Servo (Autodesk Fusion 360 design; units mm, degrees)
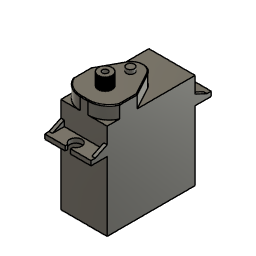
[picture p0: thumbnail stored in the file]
sketch "Esquisse3" plane through (0, 0, 0) normal (1, 0, 0) x axis (0, 0, -1)
  line L1 (0, 0) -> (0, 18.4)
  line L2 (23.4, 0) -> (0, 0)
  line L3 (23.4, 18.4) -> (23.4, 0)
  line L4 (27.7, 18.4) -> (23.4, 18.4)
  line L5 (27.7, 19.6) -> (27.7, 18.4)
  line L6 (26.5623, 19.6) -> (27.7, 19.6)
  line L7 (23.4, 21.1) -> (26.5623, 19.6)
  line L8 (23.4, 25.4) -> (23.4, 21.1)
  line L9 (0, 25.4) -> (23.4, 25.4)
  line L10 (0, 21.1) -> (0, 25.4)
  line L11 (-3.1623, 19.6) -> (0, 21.1)
  line L12 (-4.3, 19.6) -> (-3.1623, 19.6)
  line L13 (-4.3, 18.4) -> (-4.3, 19.6)
  line L14 (0, 18.4) -> (-4.3, 18.4)
  point P2 (0, 18.4)
  point P16 (0, 18.4)
  point P12 (0, 21.1)
  point P5 (23.4, 18.4)
  point P9 (23.4, 21.1)
  point P8 (26.5623, 19.6)
  point P13 (-3.1623, 19.6)
  point P1 (0, 0)
  point P3 (0, 0)
  point P14 (-4.3, 19.6)
  point P15 (-4.3, 18.4)
  vertical L1
  perpendicular L1 L2
  perpendicular L2 L3
  perpendicular L3 L4
  perpendicular L4 L5
  perpendicular L5 L6
  perpendicular L6 L8
  perpendicular L8 L9
  perpendicular L9 L10
  perpendicular L10 L12
  perpendicular L12 L13
  perpendicular L13 L14
  coincident P2 P16
  vertical P2 P12
  vertical P5 P9
  equal L5 L13
  horizontal P8 P13
  equal L7 L11
  equal L10 L14
  equal L4 L14
  coincident P1 P3
  equal L8 L10
  dimension "d1" distance L1 L3 = 23.4
  dimension "d2" distance L2 L9 = 25.4
  dimension "d3" distance L5 L13 = 32
  dimension "d4" distance P14 P15 = 1.2
  dimension "d5" distance P12 L14 = 2.7
  dimension "d6" distance P12 P13 = 3.5
extrude "Extrusion1" new body sketch "Esquisse3" along normal blind 6.15 (= "( 12.3 / 2 ) * 1 mm") and against normal blind 6.15 (= "( 12.3 / 2 ) * 1 mm")
sketch "Esquisse4" plane through (0, 25.4, 0) normal (0, 1, 0) x axis (-1, 0, 0)
  line L1 (-6.15, 0) -> (6.15, 0)
  line L2 (-6.15, -23.4) -> (-6.15, 0)
  line L3 (6.15, -23.4) -> (-6.15, -23.4)
  line L4 (6.15, 0) -> (6.15, -23.4)
  line L5 (6.15, -3.2909) -> (6.15, -7.9909)
  line L6 (0, 0) -> (1.0315, 0)
  line L7 (2.8, -14.1372) -> (6.15, -7.9909)
  line L8 (-9.0575, -15.8) -> (8.378, -15.8)
  line L9 (0, 22.5) -> (0, 1.75)
  line L10 (-2.8, -14.1372) -> (-6.15, -7.9909)
  line L11 (-6.15, -3.2909) -> (-6.15, -7.9909)
  arc A1 centre (1.0315, -5.6261) radius 5.6261 clockwise from (1.0315, 0) to (6.15, -3.2909)
  arc A2 centre (0, -12.6111) radius 3.1889 clockwise from (2.8, -14.1372) to (0, -15.8)
  arc A3 centre (0, -12.6111) radius 3.1889 clockwise from (0, -15.8) to (-2.8, -14.1372)
  arc A4 centre (-1.0315, -5.6261) radius 5.6261 clockwise from (-6.15, -3.2909) to (-1.0315, 0)
  point P6 (6.15, -7.9909)
  point P7 (6.15, -3.2909)
  point P1 (0, 0)
  point P10 (0, 0)
  point P12 (0, -15.8)
  point P21 (-6.15, -7.9909)
  point P22 (-6.15, -3.2909)
  point P8 (1.0315, 0)
  point P24 (-1.0315, 0)
  point P11 (2.8, -14.1372)
  point P20 (-2.8, -14.1372)
  point P19 (0, -15.8)
  coincident L4 P6
  coincident L4 P7
  perpendicular L2 L6
  vertical P1 P10
  coincident P1 P10
  vertical P1 P12
  tangent L7 A2
  perpendicular L4 L8
  tangent A2 L8
  coincident P12 L8
  collinear L4 L5
  tangent A1 L7
  tangent A1 L6
  symmetric P6 L9 P21
  symmetric P7 L9 P22
  symmetric P8 L9 P24
  symmetric A1 L9 A4
  symmetric P11 L9 P20
  symmetric P12 L9 P19
  symmetric A2 L9 A3
  dimension "d11" distance L6 L8 = 15.8
  dimension "d13" distance P6 P7 = 4.7
  dimension "d15" distance P6 P11 = 7
  dimension "d16" distance P11 L9 = 2.8 (= "( 5.6 / 2 ) * 1 mm")
extrude "Extrusion2" add sketch "Esquisse4" profile of L1 L2 L4 L5 A1 L6 L7 A2 A3 L10 L11 A4 along normal blind 3.4
sketch "Esquisse5" plane through (0, 28.8, 0) normal (0, 1, 0) x axis (-1, 0, 0)
  line L1 (6.15, -3.2909) -> (6.15, -7.9909)
  line L2 (-1.0315, 0) -> (1.0315, 0)
  line L3 (-6.15, -7.9909) -> (-6.15, -3.2909)
  line L4 (-2.8, -14.1372) -> (-6.15, -7.9909)
  line L5 (6.15, -7.9909) -> (2.8, -14.1372)
  line L6 (0, 22.5) -> (0, 1.75)
  line L7 (-2.5, -13.4) -> (1.9579, -13.4)
  line L8 (-3, -15.8) -> (2.2631, -15.8)
  arc A1 centre (1.0315, -5.6261) radius 5.6261 clockwise from (1.0315, 0) to (6.15, -3.2909)
  arc A2 centre (-1.0315, -5.6261) radius 5.6261 clockwise from (-6.15, -3.2909) to (-1.0315, 0)
  arc A3 centre (0, -12.6111) radius 3.1889 clockwise from (2.8, -14.1372) to (-2.8, -14.1372)
  circle C1 centre (0, -12.35) radius 1.05
  point P13 (0, -12.35)
  coincident P13 L6
  horizontal L7
  tangent C1 L7
  horizontal L8
  tangent A3 L8
  dimension "d19" diameter C1 = 2.1
  dimension "d20" distance L7 L8 = 2.4
extrude "Extrusion3" add sketch "Esquisse5" profile of C1 along normal blind 1.1
sketch "Esquisse6" plane through (0, 28.8, 0) normal (0, 1, 0) x axis (-1, 0, 0)
  line L1 (6.15, -3.2909) -> (6.15, -7.9909)
  line L2 (-1.0315, 0) -> (1.0315, 0)
  line L3 (-6.15, -7.9909) -> (-6.15, -3.2909)
  line L4 (-2.8, -14.1372) -> (-6.15, -7.9909)
  line L5 (6.15, -7.9909) -> (2.8, -14.1372)
  circle C1 centre (0, -12.35) radius 1.05
  arc A1 centre (1.0315, -5.6261) radius 5.6261 clockwise from (1.0315, 0) to (6.15, -3.2909)
  arc A2 centre (-1.0315, -5.6261) radius 5.6261 clockwise from (-6.15, -3.2909) to (-1.0315, 0)
  arc A3 centre (0, -12.6111) radius 3.1889 clockwise from (2.8, -14.1372) to (-2.8, -14.1372)
  circle C2 centre (0.0217, -5.6409) radius 1.85
  arc A4 centre (0.0217, -7.5545) radius 0.12 clockwise from (-0.0783, -7.4882) to (0.1217, -7.4882)
  arc A5 centre (0.3211, -7.5309) radius 0.12 clockwise from (0.2119, -7.4811) to (0.4095, -7.4498)
  arc A6 centre (0.6131, -7.4608) radius 0.12 clockwise from (0.4975, -7.4287) to (0.6877, -7.3669)
  arc A7 centre (0.8905, -7.3459) radius 0.12 clockwise from (0.7713, -7.3322) to (0.9495, -7.2414)
  arc A8 centre (1.1465, -7.189) radius 0.12 clockwise from (1.0266, -7.1942) to (1.1884, -7.0766)
  arc A9 centre (1.3749, -6.994) radius 0.12 clockwise from (1.2572, -7.0178) to (1.3987, -6.8764)
  arc A10 centre (1.5699, -6.7657) radius 0.12 clockwise from (1.4574, -6.8076) to (1.575, -6.6458)
  arc A11 centre (1.7268, -6.5097) radius 0.12 clockwise from (1.6223, -6.5686) to (1.7131, -6.3904)
  arc A12 centre (1.8417, -6.2322) radius 0.12 clockwise from (1.7477, -6.3068) to (1.8095, -6.1166)
  arc A13 centre (1.9118, -5.9402) radius 0.12 clockwise from (1.8306, -6.0286) to (1.8619, -5.8311)
  arc A14 centre (1.9354, -5.6409) radius 0.12 clockwise from (1.869, -5.7409) to (1.869, -5.5409)
  arc A15 centre (1.9118, -5.3415) radius 0.12 clockwise from (1.8619, -5.4507) to (1.8306, -5.2531)
  arc A16 centre (1.8417, -5.0495) radius 0.12 clockwise from (1.8095, -5.1651) to (1.7477, -4.9749)
  arc A17 centre (1.7268, -4.7721) radius 0.12 clockwise from (1.7131, -4.8913) to (1.6223, -4.7131)
  arc A18 centre (1.5699, -4.5161) radius 0.12 clockwise from (1.575, -4.636) to (1.4574, -4.4742)
  arc A19 centre (1.3749, -4.2877) radius 0.12 clockwise from (1.3987, -4.4054) to (1.2572, -4.2639)
  arc A20 centre (1.1465, -4.0927) radius 0.12 clockwise from (1.1884, -4.2052) to (1.0266, -4.0876)
  arc A21 centre (0.8905, -3.9358) radius 0.12 clockwise from (0.9495, -4.0403) to (0.7713, -3.9495)
  arc A22 centre (0.6131, -3.8209) radius 0.12 clockwise from (0.6877, -3.9149) to (0.4975, -3.8531)
  arc A23 centre (0.3211, -3.7508) radius 0.12 clockwise from (0.4095, -3.832) to (0.2119, -3.8007)
  arc A24 centre (0.0217, -3.7273) radius 0.12 clockwise from (0.1217, -3.7936) to (-0.0783, -3.7936)
  arc A25 centre (-0.2776, -3.7508) radius 0.12 clockwise from (-0.1685, -3.8007) to (-0.366, -3.832)
  arc A26 centre (-0.5696, -3.8209) radius 0.12 clockwise from (-0.454, -3.8531) to (-0.6442, -3.9149)
  arc A27 centre (-0.847, -3.9358) radius 0.12 clockwise from (-0.7278, -3.9495) to (-0.906, -4.0403)
  arc A28 centre (-1.1031, -4.0927) radius 0.12 clockwise from (-0.9832, -4.0876) to (-1.145, -4.2052)
  arc A29 centre (-1.3314, -4.2877) radius 0.12 clockwise from (-1.2138, -4.2639) to (-1.3552, -4.4054)
  arc A30 centre (-1.5264, -4.5161) radius 0.12 clockwise from (-1.414, -4.4742) to (-1.5315, -4.636)
  arc A31 centre (-1.6833, -4.7721) radius 0.12 clockwise from (-1.5788, -4.7131) to (-1.6696, -4.8913)
  arc A32 centre (-1.7982, -5.0495) radius 0.12 clockwise from (-1.7043, -4.9749) to (-1.7661, -5.1651)
  arc A33 centre (-1.8683, -5.3415) radius 0.12 clockwise from (-1.7872, -5.2531) to (-1.8185, -5.4507)
  arc A34 centre (-1.8919, -5.6409) radius 0.12 clockwise from (-1.8256, -5.5409) to (-1.8256, -5.7409)
  arc A35 centre (-1.8683, -5.9402) radius 0.12 clockwise from (-1.8185, -5.8311) to (-1.7872, -6.0286)
  arc A36 centre (-1.7982, -6.2322) radius 0.12 clockwise from (-1.7661, -6.1166) to (-1.7043, -6.3068)
  arc A37 centre (-1.6833, -6.5097) radius 0.12 clockwise from (-1.6696, -6.3904) to (-1.5788, -6.5686)
  arc A38 centre (-1.5264, -6.7657) radius 0.12 clockwise from (-1.5315, -6.6458) to (-1.414, -6.8076)
  arc A39 centre (-1.3314, -6.994) radius 0.12 clockwise from (-1.3552, -6.8764) to (-1.2138, -7.0178)
  arc A40 centre (-1.1031, -7.189) radius 0.12 clockwise from (-1.145, -7.0766) to (-0.9832, -7.1942)
  arc A41 centre (-0.847, -7.3459) radius 0.12 clockwise from (-0.906, -7.2414) to (-0.7278, -7.3322)
  arc A42 centre (-0.5696, -7.4608) radius 0.12 clockwise from (-0.6442, -7.3669) to (-0.454, -7.4287)
  arc A43 centre (-0.2776, -7.5309) radius 0.12 clockwise from (-0.366, -7.4498) to (-0.1685, -7.4811)
  point P16 (-0.0783, -7.4882)
  point P15 (0.1217, -7.4882)
  point P3 (6.15, -7.9909)
  point P4 (6.15, -3.2909)
  point P14 (0.0217, -5.6409)
  coincident C2 P16
  coincident C2 P15
  dimension "d23" diameter C2 = 3.7
  dimension "d25" distance P3 P4 = 4.7
  dimension "d26" distance P3 P14 = 2.35 (= "d25 / 2")
  dimension "d27" distance P14 P15 = 0.1
  dimension "d28" distance P14 P16 = 0.1
  dimension "d30" radius A4 = 0.12
  dimension "d32" C-Pattern1-Angle = 360
extrude "Extrusion4" add sketch "Esquisse6" profile of C2 A4 A5 A6 A7 A8 A9 A10 A11 A12 A13 A14 A15 A16 A17 A18 A19 A20 A21 A22 A23 A24 A25 A26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 along normal blind 3.3
sketch "Esquisse7" plane through (0, 32.1, 0) normal (0, 1, 0) x axis (-1, 0, 0)
  line L1 (0.0217, -3.8473) -> (0.0217, -7.4345)
  line L2 (-1.7719, -5.6409) -> (1.8154, -5.6409)
  arc A1 centre (0.0217, -5.6409) radius 1.85 clockwise from (0.2119, -7.4811) to (0.1217, -7.4882)
  arc A2 centre (0.3211, -7.5309) radius 0.12 clockwise from (0.2119, -7.4811) to (0.4095, -7.4498)
  arc A3 centre (0.0217, -5.6409) radius 1.85 clockwise from (0.4975, -7.4287) to (0.4095, -7.4498)
  arc A4 centre (0.6131, -7.4608) radius 0.12 clockwise from (0.4975, -7.4287) to (0.6877, -7.3669)
  arc A5 centre (0.0217, -5.6409) radius 1.85 clockwise from (0.7713, -7.3322) to (0.6877, -7.3669)
  arc A6 centre (0.8905, -7.3459) radius 0.12 clockwise from (0.7713, -7.3322) to (0.9495, -7.2414)
  arc A7 centre (0.0217, -5.6409) radius 1.85 clockwise from (1.0266, -7.1942) to (0.9495, -7.2414)
  arc A8 centre (1.1465, -7.189) radius 0.12 clockwise from (1.0266, -7.1942) to (1.1884, -7.0766)
  arc A9 centre (0.0217, -5.6409) radius 1.85 clockwise from (1.2572, -7.0178) to (1.1884, -7.0766)
  arc A10 centre (1.3749, -6.994) radius 0.12 clockwise from (1.2572, -7.0178) to (1.3987, -6.8764)
  arc A11 centre (0.0217, -5.6409) radius 1.85 clockwise from (1.4574, -6.8076) to (1.3987, -6.8764)
  arc A12 centre (1.5699, -6.7657) radius 0.12 clockwise from (1.4574, -6.8076) to (1.575, -6.6458)
  arc A13 centre (0.0217, -5.6409) radius 1.85 clockwise from (1.6223, -6.5686) to (1.575, -6.6458)
  arc A14 centre (1.7268, -6.5097) radius 0.12 clockwise from (1.6223, -6.5686) to (1.7131, -6.3904)
  arc A15 centre (0.0217, -5.6409) radius 1.85 clockwise from (1.7477, -6.3068) to (1.7131, -6.3904)
  arc A16 centre (1.8417, -6.2322) radius 0.12 clockwise from (1.7477, -6.3068) to (1.8095, -6.1166)
  arc A17 centre (0.0217, -5.6409) radius 1.85 clockwise from (1.8306, -6.0286) to (1.8095, -6.1166)
  arc A18 centre (1.9118, -5.9402) radius 0.12 clockwise from (1.8306, -6.0286) to (1.8619, -5.8311)
  arc A19 centre (0.0217, -5.6409) radius 1.85 clockwise from (1.869, -5.7409) to (1.8619, -5.8311)
  arc A20 centre (1.9354, -5.6409) radius 0.12 clockwise from (1.869, -5.7409) to (1.869, -5.5409)
  arc A21 centre (0.0217, -5.6409) radius 1.85 clockwise from (1.8619, -5.4507) to (1.869, -5.5409)
  arc A22 centre (1.9118, -5.3415) radius 0.12 clockwise from (1.8619, -5.4507) to (1.8306, -5.2531)
  arc A23 centre (0.0217, -5.6409) radius 1.85 clockwise from (1.8095, -5.1651) to (1.8306, -5.2531)
  arc A24 centre (1.8417, -5.0495) radius 0.12 clockwise from (1.8095, -5.1651) to (1.7477, -4.9749)
  arc A25 centre (0.0217, -5.6409) radius 1.85 clockwise from (1.7131, -4.8913) to (1.7477, -4.9749)
  arc A26 centre (1.7268, -4.7721) radius 0.12 clockwise from (1.7131, -4.8913) to (1.6223, -4.7131)
  arc A27 centre (0.0217, -5.6409) radius 1.85 clockwise from (1.575, -4.636) to (1.6223, -4.7131)
  arc A28 centre (1.5699, -4.5161) radius 0.12 clockwise from (1.575, -4.636) to (1.4574, -4.4742)
  arc A29 centre (0.0217, -5.6409) radius 1.85 clockwise from (1.3987, -4.4054) to (1.4574, -4.4742)
  arc A30 centre (1.3749, -4.2877) radius 0.12 clockwise from (1.3987, -4.4054) to (1.2572, -4.2639)
  arc A31 centre (0.0217, -5.6409) radius 1.85 clockwise from (1.1884, -4.2052) to (1.2572, -4.2639)
  arc A32 centre (1.1465, -4.0927) radius 0.12 clockwise from (1.1884, -4.2052) to (1.0266, -4.0876)
  arc A33 centre (0.0217, -5.6409) radius 1.85 clockwise from (0.9495, -4.0403) to (1.0266, -4.0876)
  arc A34 centre (0.8905, -3.9358) radius 0.12 clockwise from (0.9495, -4.0403) to (0.7713, -3.9495)
  arc A35 centre (0.0217, -5.6409) radius 1.85 clockwise from (0.6877, -3.9149) to (0.7713, -3.9495)
  arc A36 centre (0.6131, -3.8209) radius 0.12 clockwise from (0.6877, -3.9149) to (0.4975, -3.8531)
  arc A37 centre (0.0217, -5.6409) radius 1.85 clockwise from (0.4095, -3.832) to (0.4975, -3.8531)
  arc A38 centre (0.3211, -3.7508) radius 0.12 clockwise from (0.4095, -3.832) to (0.2119, -3.8007)
  arc A39 centre (0.0217, -5.6409) radius 1.85 clockwise from (0.1217, -3.7936) to (0.2119, -3.8007)
  arc A40 centre (0.0217, -3.7273) radius 0.12 clockwise from (0.1217, -3.7936) to (-0.0783, -3.7936)
  arc A41 centre (0.0217, -5.6409) radius 1.85 clockwise from (-0.1685, -3.8007) to (-0.0783, -3.7936)
  arc A42 centre (-0.2776, -3.7508) radius 0.12 clockwise from (-0.1685, -3.8007) to (-0.366, -3.832)
  arc A43 centre (0.0217, -5.6409) radius 1.85 clockwise from (-0.454, -3.8531) to (-0.366, -3.832)
  arc A44 centre (-0.5696, -3.8209) radius 0.12 clockwise from (-0.454, -3.8531) to (-0.6442, -3.9149)
  arc A45 centre (0.0217, -5.6409) radius 1.85 clockwise from (-0.7278, -3.9495) to (-0.6442, -3.9149)
  arc A46 centre (-0.847, -3.9358) radius 0.12 clockwise from (-0.7278, -3.9495) to (-0.906, -4.0403)
  arc A47 centre (0.0217, -5.6409) radius 1.85 clockwise from (-0.9832, -4.0876) to (-0.906, -4.0403)
  arc A48 centre (-1.1031, -4.0927) radius 0.12 clockwise from (-0.9832, -4.0876) to (-1.145, -4.2052)
  arc A49 centre (0.0217, -5.6409) radius 1.85 clockwise from (-1.2138, -4.2639) to (-1.145, -4.2052)
  arc A50 centre (-1.3314, -4.2877) radius 0.12 clockwise from (-1.2138, -4.2639) to (-1.3552, -4.4054)
  arc A51 centre (0.0217, -5.6409) radius 1.85 clockwise from (-1.414, -4.4742) to (-1.3552, -4.4054)
  arc A52 centre (-1.5264, -4.5161) radius 0.12 clockwise from (-1.414, -4.4742) to (-1.5315, -4.636)
  arc A53 centre (0.0217, -5.6409) radius 1.85 clockwise from (-1.5788, -4.7131) to (-1.5315, -4.636)
  arc A54 centre (-1.6833, -4.7721) radius 0.12 clockwise from (-1.5788, -4.7131) to (-1.6696, -4.8913)
  arc A55 centre (0.0217, -5.6409) radius 1.85 clockwise from (-1.7043, -4.9749) to (-1.6696, -4.8913)
  arc A56 centre (-1.7982, -5.0495) radius 0.12 clockwise from (-1.7043, -4.9749) to (-1.7661, -5.1651)
  arc A57 centre (0.0217, -5.6409) radius 1.85 clockwise from (-1.7872, -5.2531) to (-1.7661, -5.1651)
  arc A58 centre (-1.8683, -5.3415) radius 0.12 clockwise from (-1.7872, -5.2531) to (-1.8185, -5.4507)
  arc A59 centre (0.0217, -5.6409) radius 1.85 clockwise from (-1.8256, -5.5409) to (-1.8185, -5.4507)
  arc A60 centre (-1.8919, -5.6409) radius 0.12 clockwise from (-1.8256, -5.5409) to (-1.8256, -5.7409)
  arc A61 centre (0.0217, -5.6409) radius 1.85 clockwise from (-1.8185, -5.8311) to (-1.8256, -5.7409)
  arc A62 centre (-1.8683, -5.9402) radius 0.12 clockwise from (-1.8185, -5.8311) to (-1.7872, -6.0286)
  arc A63 centre (0.0217, -5.6409) radius 1.85 clockwise from (-1.7661, -6.1166) to (-1.7872, -6.0286)
  arc A64 centre (-1.7982, -6.2322) radius 0.12 clockwise from (-1.7661, -6.1166) to (-1.7043, -6.3068)
  arc A65 centre (0.0217, -5.6409) radius 1.85 clockwise from (-1.6696, -6.3904) to (-1.7043, -6.3068)
  arc A66 centre (-1.6833, -6.5097) radius 0.12 clockwise from (-1.6696, -6.3904) to (-1.5788, -6.5686)
  arc A67 centre (0.0217, -5.6409) radius 1.85 clockwise from (-1.5315, -6.6458) to (-1.5788, -6.5686)
  arc A68 centre (-1.5264, -6.7657) radius 0.12 clockwise from (-1.5315, -6.6458) to (-1.414, -6.8076)
  arc A69 centre (0.0217, -5.6409) radius 1.85 clockwise from (-1.3552, -6.8764) to (-1.414, -6.8076)
  arc A70 centre (-1.3314, -6.994) radius 0.12 clockwise from (-1.3552, -6.8764) to (-1.2138, -7.0178)
  arc A71 centre (0.0217, -5.6409) radius 1.85 clockwise from (-1.145, -7.0766) to (-1.2138, -7.0178)
  arc A72 centre (-1.1031, -7.189) radius 0.12 clockwise from (-1.145, -7.0766) to (-0.9832, -7.1942)
  arc A73 centre (0.0217, -5.6409) radius 1.85 clockwise from (-0.906, -7.2414) to (-0.9832, -7.1942)
  arc A74 centre (-0.847, -7.3459) radius 0.12 clockwise from (-0.906, -7.2414) to (-0.7278, -7.3322)
  arc A75 centre (0.0217, -5.6409) radius 1.85 clockwise from (-0.6442, -7.3669) to (-0.7278, -7.3322)
  arc A76 centre (-0.5696, -7.4608) radius 0.12 clockwise from (-0.6442, -7.3669) to (-0.454, -7.4287)
  arc A77 centre (0.0217, -5.6409) radius 1.85 clockwise from (-0.366, -7.4498) to (-0.454, -7.4287)
  arc A78 centre (-0.2776, -7.5309) radius 0.12 clockwise from (-0.366, -7.4498) to (-0.1685, -7.4811)
  arc A79 centre (0.0217, -5.6409) radius 1.85 clockwise from (-0.0783, -7.4882) to (-0.1685, -7.4811)
  arc A80 centre (0.0217, -7.5545) radius 0.12 clockwise from (-0.0783, -7.4882) to (0.1217, -7.4882)
  circle C1 centre (0.0217, -5.6409) radius 0.75
  point P123 (0.0217, -7.4345)
  point P124 (0.0217, -3.8473)
  point P125 (1.8154, -5.6409)
  point P126 (-1.7719, -5.6409)
  midpoint A80 P123
  midpoint A40 P124
  midpoint A20 P125
  midpoint A60 P126
  concentric A1 C1
  dimension "d35" diameter C1 = 1.5
extrude "Extrusion5" cut sketch "Esquisse7" profile of L1 L2 C1 to an object
fillet "Congé" radius 0.2
sketch "Esquisse8" plane through (0, 25.4, 0) normal (0, 1, 0) x axis (-1, 0, 0)
  line L1 (-6.15, 0) -> (-1.0315, 0)
  line L2 (-6.15, -3.2909) -> (-6.15, 0)
  line L3 (-2.524, 0.6) -> (2.0895, 0.6)
  line L4 (-6.15, 4.3) -> (6.15, 4.3)
  line L5 (-0.7, 3.6387) -> (0.7, 3.6387)
  line L6 (-0.7, 4.3) -> (-0.7, 3.6387)
  line L7 (0.7, 4.3) -> (-0.7, 4.3)
  line L8 (0.7, 3.6387) -> (0.7, 4.3)
  line L9 (0, 22.5) -> (0, 1.75)
  arc A1 centre (-1.0315, -5.6261) radius 5.6261 clockwise from (-6.15, -3.2909) to (-1.0315, 0)
  circle C1 centre (0, 2.2) radius 1.6
  point P13 (-0.7, 4.3)
  point P11 (0.7, 3.6387)
  point P12 (-0.7, 3.6387)
  point P6 (0, 2.2)
  horizontal L3
  tangent C1 L3
  horizontal L5
  vertical L6
  horizontal L7
  vertical L8
  coincident L4 P13
  coincident C1 P11
  coincident C1 P12
  coincident P6 L9
  dimension "d40" diameter C1 = 3.2
  dimension "d41" distance L3 L4 = 3.7
  dimension "d42" distance P11 P12 = 1.4
extrude "Extrusion6" cut sketch "Esquisse8" profile of C1 L4 L5 L6 L7 L8 L9 to an object
work_plane "Plan de construction"
mirror "Symétrie miroir" mirrorStitchTolerance 0.1
sketch "Esquisse9" plane through (0, 19.6, 0) normal (0, 1, 0) x axis (-1, 0, 0)
  line L1 (6.15, 3.1623) -> (1.2783, 3.1623)
  line L2 (6.15, 4.3) -> (6.15, 3.1623)
  line L3 (0.7, 4.3) -> (6.15, 4.3)
  line L4 (0.7, 3.6387) -> (0.7, 4.3)
  line L5 (-5.25, 3.1623) -> (5.25, 3.1623)
  line L6 (-5.25, 0) -> (-5.25, 3.1623)
  line L7 (5.25, 0) -> (-5.25, 0)
  line L8 (5.25, 3.1623) -> (5.25, 0)
  line L9 (6.15, 0) -> (6.15, 3.1623)
  line L10 (-6.15, 3.1623) -> (-6.15, 0)
  line L11 (-1.0315, 0) -> (1.0315, 0)
  line L12 (-1.0315, 0) -> (1.0315, 0)
  line L13 (7.38, -11.7) -> (-7.38, -11.7)
  line L14 (5.25, -23.4) -> (-5.25, -23.4)
  line L15 (-5.25, -26.5623) -> (5.25, -26.5623)
  line L16 (5.25, -26.5623) -> (5.25, -23.4)
  line L17 (-1.0315, -23.4) -> (1.0315, -23.4)
  line L18 (-1.0315, -23.4) -> (1.0315, -23.4)
  line L19 (-5.25, -23.4) -> (-5.25, -26.5623)
  arc A1 centre (0, 2.2) radius 1.6 clockwise from (0.7, 3.6387) to (1.2783, 3.1623)
  arc A2 centre (0, -25.6) radius 1.6 clockwise from (1.2783, -26.5623) to (0.7, -27.0387)
  point P8 (5.25, 3.1623)
  point P16 (1.0315, 0)
  point P18 (1.0315, 0)
  point P17 (-1.0315, 0)
  point P19 (-1.0315, 0)
  point P1 (0, 0)
  point P31 (0, -23.4)
  point P2 (1.2783, 3.1623)
  point P24 (1.2783, -26.5623)
  point P3 (0.7, 3.6387)
  point P27 (0.7, -27.0387)
  point P5 (6.15, 3.1623)
  point P22 (6.15, -26.5623)
  point P32 (5.25, -26.5623)
  point P9 (-5.25, 3.1623)
  point P28 (-5.25, -26.5623)
  point P10 (-5.25, 0)
  point P25 (-5.25, -23.4)
  point P11 (5.25, 0)
  point P23 (5.25, -23.4)
  point P12 (6.15, 3.1623)
  point P34 (6.15, -26.5623)
  point P13 (6.15, 0)
  point P36 (6.15, -23.4)
  point P35 (1.0315, -23.4)
  point P26 (-1.0315, -23.4)
  point P30 (1.0315, -23.4)
  point P33 (-1.0315, -23.4)
  horizontal L5
  vertical L6
  horizontal L7
  vertical L8
  coincident L1 P8
  collinear L7 L11
  coincident P16 P18
  coincident P17 P19
  symmetric P1 L13 P31
  symmetric P2 L13 P24
  symmetric P3 L13 P27
  symmetric A1 L13 A2
  symmetric P5 L13 P22
  symmetric P8 L13 P32
  symmetric P9 L13 P28
  symmetric P10 L13 P25
  symmetric P11 L13 P23
  symmetric P12 L13 P34
  symmetric P13 L13 P36
  symmetric P16 L13 P35
  symmetric P17 L13 P26
  symmetric P18 L13 P30
  symmetric P19 L13 P33
  dimension "d47" distance L8 L9 = 0.9
  dimension "d48" distance L6 L10 = 0.9 (= "d47")
extrude "Extrusion7" cut sketch "Esquisse9" profile of L1 L5 L6 L7 L8 L11 L12 L14 L15 L16 L17 L18 L19 no distance stored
